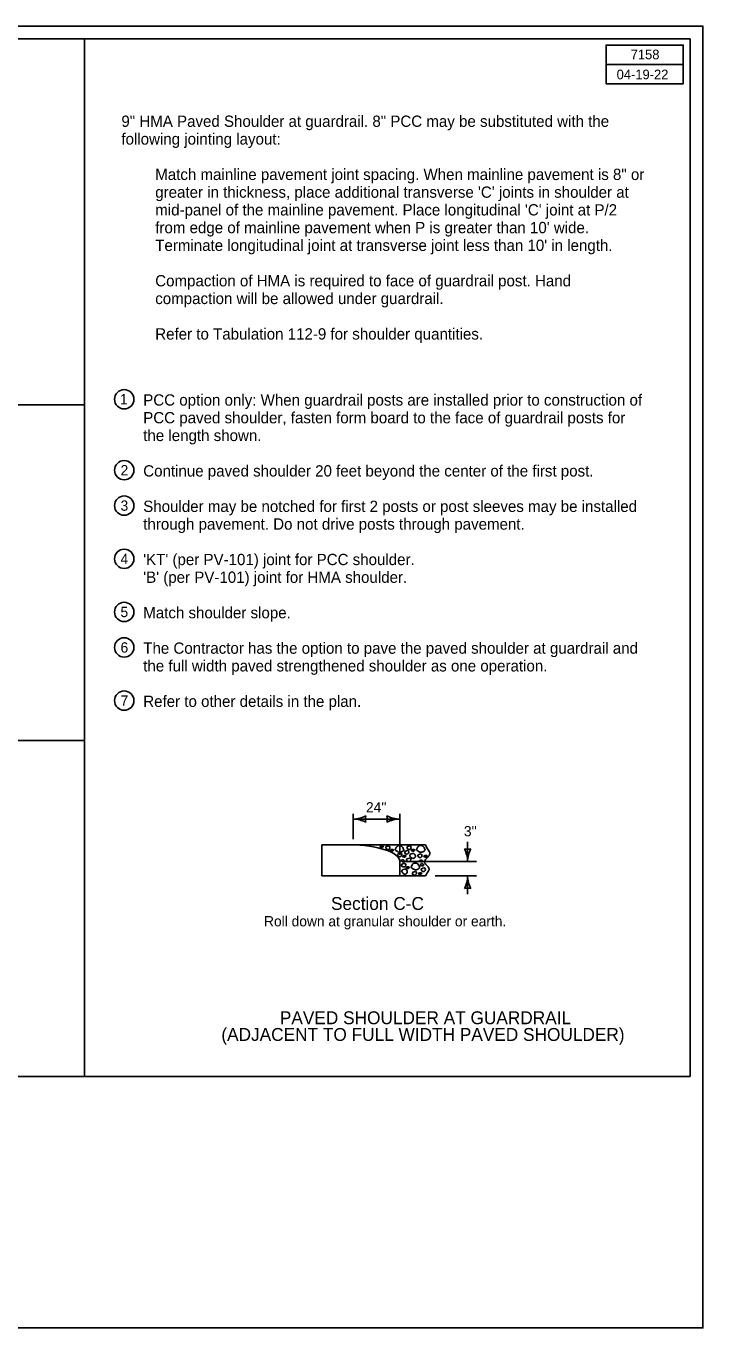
# Model space of a CAD drawing. Extents: x 10133 to 81668, y 7924 to 12229.
# Drawn here: x 12217 to 13268, y 7924 to 9944 of the extents above; entities that cross this region are included whole.
import ezdxf

# ---------------------------------------------------------------- set-up
doc = ezdxf.new("R2010")
doc.units = 0
for name, color, linetype in [('Cell', 7, 'Continuous'), ('dsnCellsNorthArrow', 7, 'Continuous'), ('dsnStdNameDate', 7, 'Continuous'), ('dsnTextFinalPlan', 7, 'Continuous'), ('Level 1', 7, 'Continuous'), ('Level 12', 7, 'Continuous'), ('Level 4', 7, 'Continuous'), ('Level 5', 7, 'Continuous'), ('Level 6', 7, 'Continuous'), ('SheetBorder', 7, 'Continuous')]:
    doc.layers.add(name, color=color, linetype=linetype)

msp = doc.modelspace()

# ---------------------------------------------------------------- linework, layer by layer
at = {"layer": 'Cell'}
for p, q in [((12719.3, 8673.7), (12676.2, 8673.7)), ((12676.2, 8673.7), (12676.2, 8625.7)), ((12797.2, 8625.7), (12797.2, 8647.5)), ((12676.2, 8625.7), (12797.2, 8625.7))]:
    msp.add_line(p, q, dxfattribs=at)
msp.add_lwpolyline([(12719.3, 8673.6), (12719.3, 8673.7)], dxfattribs=at)
msp.add_ellipse((12719.3, 8647.5), major_axis=(77.9, 0), ratio=0.335273, start_param=0, end_param=1.570796, dxfattribs=at)
at = {"layer": 'dsnStdNameDate'}
for points in [[(12768.9, 8669.4), (12769.8, 8669.2), (12770.3, 8669.2), (12772.7, 8671.6), (12768.7, 8672.4), (12765.2, 8670.3), (12768.1, 8669.6), (12768.9, 8669.4)], [(12775.4, 8669.9), (12775.4, 8670.5), (12775.8, 8670.3), (12780.3, 8673), (12782.7, 8669.8), (12780.6, 8665.7), (12775.5, 8666.8), (12775.3, 8669.3), (12775.4, 8669.9)], [(12784.6, 8663.9), (12785.4, 8663.7), (12785.9, 8663.7), (12788.4, 8666.1), (12784.3, 8666.9), (12780.9, 8664.8), (12783.7, 8664.1), (12784.6, 8663.9)], [(12790.2, 8666.1), (12790, 8666.6), (12790.5, 8666.3), (12792.4, 8672.7), (12800.7, 8673), (12803.4, 8665.7), (12803.6, 8664.9), (12798.8, 8661.2), (12792.1, 8663.3), (12790.5, 8665.7), (12790.2, 8666.1)], [(12808.3, 8669.9), (12808.3, 8670.5), (12808.7, 8670.3), (12813.3, 8673), (12815.7, 8669.8), (12813.5, 8665.7), (12808.4, 8666.8), (12808.3, 8669.3), (12808.3, 8669.9)], [(12817.5, 8663.9), (12818.3, 8663.7), (12818.9, 8663.7), (12821.3, 8666.1), (12817.3, 8666.9), (12813.8, 8664.8), (12816.6, 8664.1), (12817.5, 8663.9)], [(12823.2, 8666.1), (12822.9, 8666.6), (12823.4, 8666.3), (12825.3, 8672.7), (12833.6, 8673), (12836.3, 8665.7), (12836.6, 8664.9), (12831.7, 8661.2), (12825, 8663.3), (12823.4, 8665.7), (12823.2, 8666.1)], [(12793.7, 8658.7), (12793.8, 8659.2), (12794.1, 8659.1), (12798.7, 8661.7), (12801.1, 8658.5), (12799, 8654.5), (12793.9, 8655.6), (12793.7, 8658.1), (12793.7, 8658.7)], [(12799.1, 8649), (12798.7, 8649.5), (12799.1, 8649.8), (12803.4, 8651.2), (12804.7, 8647.7), (12801.5, 8646.9), (12799.5, 8648.5), (12799.1, 8649)], [(12803.9, 8654.7), (12804.7, 8654.5), (12805.2, 8654.5), (12807.6, 8656.9), (12803.6, 8657.7), (12800.1, 8655.6), (12803, 8654.8), (12803.9, 8654.7)], [(12804.8, 8662.7), (12804.8, 8663.3), (12805.2, 8663.1), (12809.7, 8665.8), (12812.1, 8662.6), (12810, 8658.6), (12804.9, 8659.7), (12804.7, 8662.2), (12804.8, 8662.7)], [(12807.6, 8650.9), (12807.7, 8651.5), (12808, 8651.3), (12812.6, 8654), (12815, 8650.8), (12812.8, 8646.8), (12807.8, 8647.8), (12807.6, 8650.3), (12807.6, 8650.9)], [(12812.8, 8656.7), (12812.3, 8657.9), (12812.4, 8658.2), (12817, 8661.2), (12821, 8659.3), (12822.1, 8654), (12815.9, 8651.3), (12813.4, 8655.6), (12812.8, 8656.7)], [(12814.7, 8639), (12814.5, 8639.5), (12815, 8639.2), (12816.9, 8645.6), (12825.2, 8645.8), (12827.9, 8638.6), (12828.1, 8637.8), (12823.3, 8634.1), (12816.6, 8636.2), (12815, 8638.5), (12814.7, 8639)], [(12825, 8657.3), (12825.1, 8657.9), (12825.4, 8657.7), (12830, 8660.4), (12832.4, 8657.2), (12830.3, 8653.2), (12825.2, 8654.3), (12825, 8656.8), (12825, 8657.3)], [(12827.8, 8648.6), (12827.4, 8649), (12827.7, 8649.4), (12832, 8650.7), (12833.3, 8647.3), (12830.1, 8646.5), (12828.2, 8648.1), (12827.8, 8648.6)], [(12836.8, 8654.7), (12837.6, 8654.5), (12838.2, 8654.5), (12840.6, 8656.9), (12836.6, 8657.7), (12833.1, 8655.6), (12835.9, 8654.8), (12836.8, 8654.7)], [(12800.3, 8632.2), (12799.7, 8633.4), (12799.9, 8633.7), (12804.4, 8636.7), (12808.5, 8634.8), (12809.5, 8629.4), (12803.4, 8626.8), (12800.9, 8631), (12800.3, 8632.2)], [(12799.9, 8642.8), (12799.9, 8643.3), (12800.3, 8643.2), (12804.8, 8645.8), (12807.2, 8642.6), (12805.1, 8638.6), (12800, 8639.7), (12799.8, 8642.2), (12799.9, 8642.8)], [(12809.1, 8636.8), (12809.9, 8636.6), (12810.5, 8636.6), (12812.9, 8639), (12808.9, 8639.8), (12805.4, 8637.7), (12808.2, 8637), (12809.1, 8636.8)], [(12816.6, 8630.2), (12816.7, 8630.8), (12817, 8630.6), (12821.6, 8633.3), (12824, 8630.1), (12821.8, 8626.1), (12816.8, 8627.1), (12816.6, 8629.6), (12816.6, 8630.2)], [(12828.4, 8627.5), (12829.2, 8627.4), (12829.7, 8627.4), (12832.2, 8629.8), (12828.1, 8630.6), (12824.7, 8628.4), (12827.5, 8627.7), (12828.4, 8627.5)], [(12829.1, 8642.5), (12828.7, 8643), (12829, 8643.3), (12833.3, 8644.7), (12834.6, 8641.2), (12831.4, 8640.4), (12829.5, 8642), (12829.1, 8642.5)], [(12830.2, 8635.6), (12830.2, 8636.2), (12830.6, 8636), (12835.2, 8638.7), (12837.6, 8635.5), (12835.4, 8631.5), (12830.3, 8632.6), (12830.2, 8635.1), (12830.2, 8635.6)]]:
    msp.add_open_spline(points, degree=3, dxfattribs=at)
at = {"layer": 'dsnTextFinalPlan'}
for p, q in [((13247.9, 9924.4), (13247.9, 9924.4)), ((12676.2, 8673.7), (12676.2, 8625.7)), ((12676.2, 8673.7), (12719.3, 8673.6)), ((12719.3, 8673.6), (12837, 8673.6)), ((12797.2, 8647.5), (12797.2, 8625.7)), ((12676.2, 8625.7), (12797.2, 8625.7)), ((12797.2, 8625.7), (12837, 8625.7))]:
    msp.add_line(p, q, dxfattribs=at)
msp.add_lwpolyline([(13237, 9914.4), (13237, 9854.4), (13117.3, 9854.4), (13117.3, 9914.4), (13237, 9914.4), (13237, 9884.4), (13117.3, 9884.4)], dxfattribs=at)
msp.add_ellipse((12719.3, 8647.5), major_axis=(77.9, 0), ratio=0.335273, start_param=0, end_param=1.570796, dxfattribs=at)
msp.add_spline([(12837, 8673.6), (12838.4, 8670.4), (12840.3, 8667.3), (12842.2, 8664.2), (12843.6, 8661.1), (12843.7, 8659.4), (12843, 8657.6), (12840.2, 8654.2), (12837, 8650.7), (12835.9, 8648.9), (12835.6, 8648), (12835.5, 8647.2), (12835.5, 8646.8), (12835.8, 8645.6), (12836.8, 8644), (12839.8, 8640.8), (12842.3, 8637.6), (12842.7, 8636), (12842.6, 8635.3), (12842.5, 8634.9), (12842.3, 8634.5), (12837, 8625.7)], degree=3, dxfattribs=at)
at = {"layer": 'Level 1'}
for p, q in [((10152.2, 9924.4), (13247.9, 9924.4)), ((13247.9, 9924.4), (13247.9, 8314.4)), ((10152.2, 8314.4), (13247.9, 8314.4))]:
    msp.add_line(p, q, dxfattribs=at)
at = {"layer": 'Level 12'}
for centre in [(12369.6, 9364.9), (12369.6, 9254.9), (12369.6, 9199.9), (12369.6, 9117.4), (12369.6, 9034.9), (12369.6, 8979.9), (12369.6, 8897.4)]:
    msp.add_circle(centre, 15, dxfattribs=at)
at = {"layer": 'Level 4'}
for p, q in [((12307.8, 8314.4), (12307.8, 9924.4)), ((12307.8, 9356.4), (10152.2, 9356.4)), ((12307.8, 8835.4), (10152.2, 8835.4))]:
    msp.add_line(p, q, dxfattribs=at)
at = {"layer": 'Level 5'}
for p, q in [((12724.6, 8682.2), (12724.6, 8721.5)), ((12724.6, 8713.6), (12797.2, 8713.6)), ((12797.2, 8721.5), (12797.2, 8658)), ((12902.3, 8678.4), (12902.3, 8647.5)), ((12804, 8647.5), (12916.1, 8647.5)), ((12852, 8625.7), (12916.1, 8625.7)), ((12902.3, 8625.7), (12902.3, 8597.1))]:
    msp.add_line(p, q, dxfattribs=at)
for centre, radius, start, end in [((12724.6, 8756.1), 42.5, 270, 298.0725), ((12724.6, 8671.1), 42.5, 61.9275, 90), ((12760.3, 8713.6), 16.4, 162.2666, 197.7334), ((12761.5, 8713.6), 16.4, 342.2666, 17.7334), ((12797.2, 8756.1), 42.5, 241.9275, 270), ((12797.2, 8671.1), 42.5, 90, 118.0725), ((12902.3, 8683.1), 16.4, 252.2666, 287.7334), ((12859.8, 8647.5), 42.5, 0, 28.0725), ((12944.8, 8647.5), 42.5, 151.9275, 180), ((12859.8, 8625.7), 42.5, 331.9275, 360), ((12944.8, 8625.7), 42.5, 180, 208.0725), ((12902.3, 8590), 16.4, 72.2666, 107.7334)]:
    msp.add_arc(centre, radius, start, end, dxfattribs=at)
at = {"layer": 'SheetBorder'}
msp.add_lwpolyline([(10132.5, 9944), (13267.5, 9944), (13267.5, 7924), (10132.5, 7924)], close=True, dxfattribs=at)

# ---------------------------------------------------------------- texts
at = {"layer": 'dsnCellsNorthArrow'}
for s, p in [('7158', (13155.4, 9892.4)), ('04-19-22', (13133.6, 9861.4))]:
    msp.add_text(s, height=15, dxfattribs=at).set_placement(p)
at = {"layer": 'Level 12'}
for s, height, p in [('9" HMA Paved Shoulder at guardrail. 8" PCC may be substituted with the', 17.5, (12365.2, 9787.6)), ('following jointing layout:', 17.5, (12365.2, 9760.1)), ('Match mainline pavement joint spacing. When mainline pavement is 8" or ', 17.5, (12417.7, 9705.1)), ("greater in thickness, place additional transverse 'C' joints in shoulder at ", 17.5, (12417.7, 9677.6)), ("mid-panel of the mainline pavement. Place longitudinal 'C' joint at P/2 ", 17.5, (12417.7, 9650.1)), ("from edge of mainline pavement when P is greater than 10' wide. ", 17.5, (12417.7, 9622.6)), ("Terminate longitudinal joint at transverse joint less than 10' in length.", 17.5, (12417.7, 9595.1)), ('Compaction of HMA is required to face of guardrail post. Hand ', 17.5, (12417.7, 9540.1)), ('compaction will be allowed under guardrail.', 17.5, (12417.7, 9512.6)), ('Refer to Tabulation 112-9 for shoulder quantities.', 17.5, (12417.7, 9457.6)), ('1', 16, (12362.8, 9356.9)), ('PCC option only: When guardrail posts are installed prior to construction of ', 17.5, (12399.1, 9355.1)), ('PCC paved shoulder, fasten form board to the face of guardrail posts for ', 17.5, (12399.1, 9327.6)), ('the length shown.', 17.5, (12399.1, 9300.1)), ('2', 16, (12364, 9246.9)), ('Continue paved shoulder 20 feet beyond the center of the first post.', 17.5, (12399.1, 9245.1)), ('3', 16, (12363.9, 9191.9)), ('Shoulder may be notched for first 2 posts or post sleeves may be installed ', 17.5, (12399.1, 9190.1)), ('through pavement. Do not drive posts through pavement.', 17.5, (12399.1, 9162.6)), ('4', 16, (12363.9, 9109.4)), ("'KT' (per PV-101) joint for PCC shoulder.", 17.5, (12399.1, 9107.6)), ("'B' (per PV-101) joint for HMA shoulder.", 17.5, (12399.1, 9080.1)), ('5', 16, (12363.8, 9026.9)), ('Match shoulder slope.', 17.5, (12399.1, 9025.1)), ('6', 16, (12363.9, 8971.9)), ('The Contractor has the option to pave the paved shoulder at guardrail and ', 17.5, (12399.1, 8970.1)), ('the full width paved strengthened shoulder as one operation.', 17.5, (12399.1, 8942.6)), ('7', 16, (12363.9, 8889.4)), ('Refer to other details in the plan.', 17.5, (12399.1, 8887.6))]:
    msp.add_text(s, height=height, dxfattribs=at).set_placement(p)
at = {"layer": 'Level 5'}
for s, p in [("24''", (12744.7, 8723.8)), ("3'' ", (12896.6, 8686.8))]:
    msp.add_text(s, height=16, dxfattribs=at).set_placement(p)
at = {"layer": 'Level 6'}
for s, height, p in [('Section C-C', 20, (12690.4, 8572.6)), ('Roll down at granular shoulder or earth.', 16, (12586.5, 8547.1)), ('PAVED SHOULDER AT GUARDRAIL', 20, (12611.1, 8395.3)), ('(ADJACENT TO FULL WIDTH PAVED SHOULDER)', 20, (12520.3, 8369.4))]:
    msp.add_text(s, height=height, dxfattribs=at).set_placement(p)

doc.saveas('drawing.dxf')
